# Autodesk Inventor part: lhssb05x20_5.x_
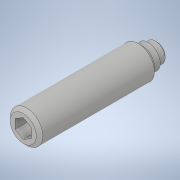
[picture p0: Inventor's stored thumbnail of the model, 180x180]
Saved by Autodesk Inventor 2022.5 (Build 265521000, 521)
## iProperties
Created: 2021-02
Part Number: lhssb05x20_5.x_
Material: 一般
Document SubType Name: Modeling
Designer: ImaoCorp
Density: 1 g/cm^3
Appearance: 既定
Sending System: SOLIDWORKS 2019-2019304
MC: AMD64
MC_MODEL: Intel64 Family 6 Model 60 Stepping 3, GenuineIntel
OS: Windows_NT
FRU: Parasolid Version 31.0, build 290,  9- 1-2019
FORMAT: text
GUISE: transmit
KEY: lhssb05x20_5
FILE: lhssb05x20_5.x_t
DATE: Mon Feb 22 14:56:19 2021
Author: ImaoCorp
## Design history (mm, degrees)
feature "Base1"
node "ソリッド1"
